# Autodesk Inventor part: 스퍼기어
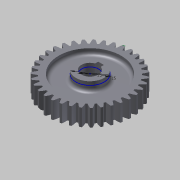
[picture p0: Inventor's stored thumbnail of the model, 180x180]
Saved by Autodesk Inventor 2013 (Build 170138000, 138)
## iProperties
Created: 2013-08
Part Number: 스퍼기어
Material: 강
Document SubType Name: Modeling
Designer: 한국산업디자인학원
Categories: <?xml version="1.0" encoding="UTF-16"?> <MemberInstance><Categories><FamilyTemplate><FamilyTemplateParameter ValueType="xs:double" Id="1" ObjectReferenceKey="da
Density: 1 g/cm^3
CustomPartVersion: 1
Author: 한국산업디자인학원
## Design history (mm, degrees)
sketch "Sketch1"
  geometry: C1 r 37 at (0, 0)
  constraints: 1 centre point
  dimensions: "d0" = 74 diameter of C1 (= da_da)
extrude "Extrusion1" new body sketch "Sketch1" distance "d1" = 15 (= da_b); taper "d2" = 0 deg
workplane "Work Plane2"
feature "피치 지름" dims "d4" = 10, "d5" = 0
workplane "Work Plane8"
workplane "Work Plane9"
feature "스퍼 기어" dims "da_b" = 15, "da_d" = 70, "da_aw" = 70, "da_da" = 74, "da_df" = 65, "da_dw" = 70, angle "da_beta" = 0 deg, "da_lefttooth" = 0, "da_righttooth" = 0
sketch "스케치3"
  geometry: C1 r 7.5 at (0, 0); C2 r 12.5 at (0, 0); A1 r 37 centre (0, 0) between (-5.788, 36.544) and (-7.422, 36.248) reference
  constraints: 2 centre point, 2 coincident
  dimensions: "d49" = 15 diameter of C1; "d50" = 25 diameter of C2
extrude "돌출2" join sketch "스케치3" distance "d51" = 3; taper "d52" = 0 deg
sketch "스케치4"
  geometry: C1 r 12.5 at (0, 0); A1 r 32.5 centre (0, 0) between (9.347, 31.127) and (7.941, 31.515) reference
  constraints: 1 centre point, 1 coincident
  dimensions: "d53" = 25 diameter of C1
extrude "돌출3" join sketch "스케치4" distance "d54" = 13; taper "d55" = 0 deg
extrude "돌출4" cut sketch "스케치3" distance "d56" = 28; taper "d57" = 0 deg
sketch "스케치5"
  geometry: C1 r 12.5 at (0, 0) reference; C2 r 27.5 at (0, 0); C3 r 12.5 at (0, 0); A1 r 32.5 centre (0, 0) between (9.347, 31.127) and (7.941, 31.515) reference
  constraints: 2 centre point, 2 coincident
  dimensions: "d58" = 55 diameter of C2; "d59" = 25 diameter of C3
extrude "돌출5" cut sketch "스케치5" distance "d60" = 5; taper "d61" = 0 deg
sketch "스케치6"
  geometry: C1 r 12.5 at (0, 0) reference; C2 r 27.5 at (0, 0); C3 r 12.5 at (0, 0)
  constraints: 2 centre point, 2 coincident
  dimensions: "d62" = 55 diameter of C2; "d63" = 25 diameter of C3
extrude "돌출6" cut sketch "스케치6" distance "d64" = 5; taper "d65" = 0 deg
fillet "모깎기1" dims "d66" = 3
sketch "스케치7"
  geometry: L1 (-2.5, 9.8)-(2.5, 9.8); L2 (2.5, 9.8)-(2.5, 4.8); L3 (2.5, 4.8)-(-2.5, 4.8); L4 (-2.5, 4.8)-(-2.5, 9.8); C1 r 7.5 at (0, 0) reference; 1 further point
  constraints: 8 end point, 2 parallel, 1 horizontal, 1 midpoint, 1 perpendicular, 1 vertical alignment
  dimensions: "d67" = 5 distance between parallel lines of L2 L4; "d68" = 5 distance between parallel lines of L3 L1; "d69" = 9.8 distance from line of C1.centre L1
extrude "돌출7" cut sketch "스케치7" distance "d70" = 31; taper "d71" = 0 deg
body "Solid1"
sketch "Sketch2"
  geometry: C1 r 37 at (0, 0) reference; C2 r 35 at (0, 0)
  constraints: 1 centre point, 1 coincident
  dimensions: "d3" = 70 diameter of C2 (= da_dw)
body "Srf1"
other parameters: "d17" = 0, "d34" = 0.8976 (computed from da_z), "d39" = 0, "d41" = 0, "d47" = 0, "d48" = 0
